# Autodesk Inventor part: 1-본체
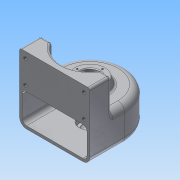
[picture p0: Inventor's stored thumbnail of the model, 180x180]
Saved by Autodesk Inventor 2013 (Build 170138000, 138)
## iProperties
Created: 2015-02
Part Number: 1-본체
Material: 알루미늄 6061
Document SubType Name: Modeling
Designer: Administrator
Density: 2.40731 g/cm^3
Mass: 511.374 g
Surface Area: 706.547 cm^2
Volume: 212.425 cm^3
Author: Administrator
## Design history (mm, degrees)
sketch "스케치1"
  geometry: L1 (-50, 0)-(-50, -50); L2 (50, 0)-(50, -50); L3 (-50, -50)-(50, -50); A1 r 50 centre (0, 0) between (-50, 0) and (50, 0); 1 further point
  constraints: 6 end point, 2 point on circle, 2 tangent, 1 centre point, 1 coincident, 1 parallel, 1 vertical
  dimensions: "d0" = 50 radius of A1; "d2" = 50 distance of L2.start L2.end; "d3" = 50 distance of L1.start L1.end
extrude "돌출1" new body sketch "스케치1" distance "d4" = 50; taper "d5" = 0 deg
feature "쉘2" dims "d43" = 4
sketch "스케치6"
  geometry: L1 (-50, 0)-(-50, -50) reference; L2 (-50, -50)-(50, -50) reference; L3 (50, -50)-(50, 0) reference; L4 (-34.641, -20)-(-50, -20); L5 (-50, -20)-(-50, -50); L6 (50, -50)-(-50, -50); L7 (50, -50)-(50, -20); L8 (34.641, -20)-(50, -20); A1 r 50 centre (0, 0) between (50, 0) and (-50, 0) reference; A2 r 40 centre (0, 0) between (-34.641, -20) and (34.641, -20)
  constraints: 10 end point, 2 collinear, 2 perpendicular, 2 point on circle, 2 point on line, 1 centre point, 1 coincident
  dimensions: "d44" = 40 radius of A2; "d46" = 30 distance between parallel lines of L6 L8; "d47" = 30 distance between parallel lines of L2 L4
extrude "돌출4" join sketch "스케치6" distance "d48" = 45; taper "d49" = 0 deg
sketch "스케치7"
  geometry: L1 (-50, -50)-(50, -50) reference; C1 r 25 at (0, 0); A1 r 50 centre (0, 0) between (50, 0) and (-50, 0) reference
  constraints: 1 centre point, 1 coincident
  dimensions: "d50" = 50 distance from line of L1 C1.centre; "d51" = 50 diameter of C1
extrude "돌출5" join sketch "스케치7" distance "d52" = 10; taper "d53" = -20 deg
hole "구멍3" diameter "d56" = 20; stored, may be unused: countersink angle "d60" = 90 deg, drill point angle "d62" = 0 deg; dims "d54" = 10, "d55" = 10, "d57" = 6, "d58" = 28, "d59" = 10, "d61" = 14
sketch "스케치8"
  geometry: C1 r 20 at (0, 0); A1 r 50 centre (0, 0) between (50, 0) and (-50, 0) reference
  constraints: 1 centre point, 1 coincident
  dimensions: "d63" = 40 diameter of C1
extrude "돌출6" join sketch "스케치8" distance "d65" = 9; taper "d66" = 0 deg
sketch "스케치9"
  geometry: C1 r 20 at (0, 0) reference; A1 r 46 centre (0, 0) between (46, 0) and (-46, 0) reference
hole "구멍4" sketch "스케치9" at (0, 0) diameter "d67" = 20; stored, may be unused: countersink angle "d71" = 90 deg, drill point angle "d73" = 0 deg; dims "d68" = 6, "d69" = 28, "d70" = 8, "d72" = 10
sketch "스케치10"
  geometry: C1 r 14 at (0, 0) reference; C2 r 21.36 at (0, 0) reference; A1 r 18 centre (0, 0) between (0, 18) and (-18, 0); 2 further points
  constraints: 4 point on circle, 2 horizontal alignment, 2 vertical alignment, 1 centre point, 1 coincident
  dimensions: "d74" = 36 diameter of A1
hole "구멍5" sketch "스케치10" at (0, 18), (-18, 0), (18, 0), (0, -18) diameter "d76" = 2.459; stored, may be unused: countersink angle "d80" = 90 deg, drill point angle "d82" = 118 deg; dims "d77" = 6, "d78" = 28, "d79" = 8, "d81" = 9
sketch "스케치12"
  geometry: L1 (0, 95)-(100, 95) reference; L2 (8.25, 86)-(91.75, 86); L3 (91.75, 86)-(91.75, 53); L4 (91.75, 53)-(8.25, 53); L5 (8.25, 53)-(8.25, 86); 7 further points
  constraints: 8 end point, 4 coincident, 2 midpoint, 2 parallel, 1 horizontal, 1 perpendicular, 1 vertical alignment
  dimensions: "d94" = 83.5 distance of L2.start L2.end; "d96" = 9 distance between parallel lines of L1 L2; "d97" = 33 distance of L2.end L3.end
hole "구멍7" sketch "스케치12" at (8.25, 86), (8.25, 53), (91.75, 53), (91.75, 86) diameter "d98" = 5.134; stored, may be unused: countersink angle "d102" = 90 deg, drill point angle "d104" = 118 deg; dims "d99" = 10, "d100" = 28, "d101" = 8, "d103" = 13
node "작업 평면1"
sketch "스케치13"
  geometry: L1 (50, 0)-(-50, 0) reference; 3 further points
  constraints: 1 midpoint, 1 vertical alignment, 1 other
  dimensions: "d105" = 25 distance of point (0, 0) point (0, 25)
feature "엠보싱1" sketch "스케치13" dims "d3" = 50, "d106" = 0.5, "d107" = 0
fillet "모깎기2" dims "d108" = 10, "d109" = 6, "d110" = 3, "d111" = 0.3
chamfer "모따기1" distance "d112" = 1; stored, may be unused: second distance "d113" = 2, angle "d114" = 45 deg
node "솔리드1"
